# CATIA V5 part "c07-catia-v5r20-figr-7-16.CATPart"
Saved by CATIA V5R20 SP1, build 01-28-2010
Part number: Part2
Bounding box of the stored display mesh (mm): x -50 to 50, y -65 to 65, z 0 to 28
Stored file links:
  D:\v5_r20\psrt_files_downloaded\c07-catia-v5r20-prt\c07-catia-v5r20-figr-7-16.CATPart
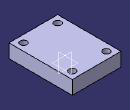
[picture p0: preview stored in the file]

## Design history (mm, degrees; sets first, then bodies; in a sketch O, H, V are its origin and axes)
Body1 (main body)
  Sketch1 on xy-plane, origin (0, 0, 0), H (1, 0, 0), V (0, 1, 0)
    line L1 (-50, 65) -> (50, 65)
    line L2 (50, 65) -> (50, -65)
    line L3 (50, -65) -> (-50, -65)
    line L4 (-50, -65) -> (-50, 65)
    axis line L5 (50, -65) -> (-50, 65)
    length L3 = 100
    length L2 = 130
    horizontal: L1 H, L3 H
    vertical: L2 V, L4 V
    midpoint: O L5
  Pad1: profile Sketch1, direction (0, 0, 1), length 28
  Sketch2 on face of Pad1, origin (25.9302, -33.7092, 28), H (1, 0, 0), V (0, 1, 0)
    point P1 (9.0698, -16.2908)
    reference projected line E1 (-75.9302, -31.2908) -> (24.0698, -31.2908) from edge [face of Pad1 | face of Pad1]
    reference projected line E2 (24.0698, -31.2908) -> (24.0698, 98.7092) from edge [face of Pad1 | face of Pad1]
    distance P1 E1 = 15
    distance P1 E2 = 15
  Hole1: placed by Sketch2, at (35, -50, 28) direction (0, 0, -1), diameter 14, through (limit type 3)
  RectPattern1: of Hole1, direction 1 instances 2, spacing 100, along edge [face of Pad1 | face of Pad1], direction 2 instances 2, spacing 70, along edge [face of Pad1 | face of Pad1]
